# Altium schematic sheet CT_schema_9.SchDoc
size 382 x 278 mm
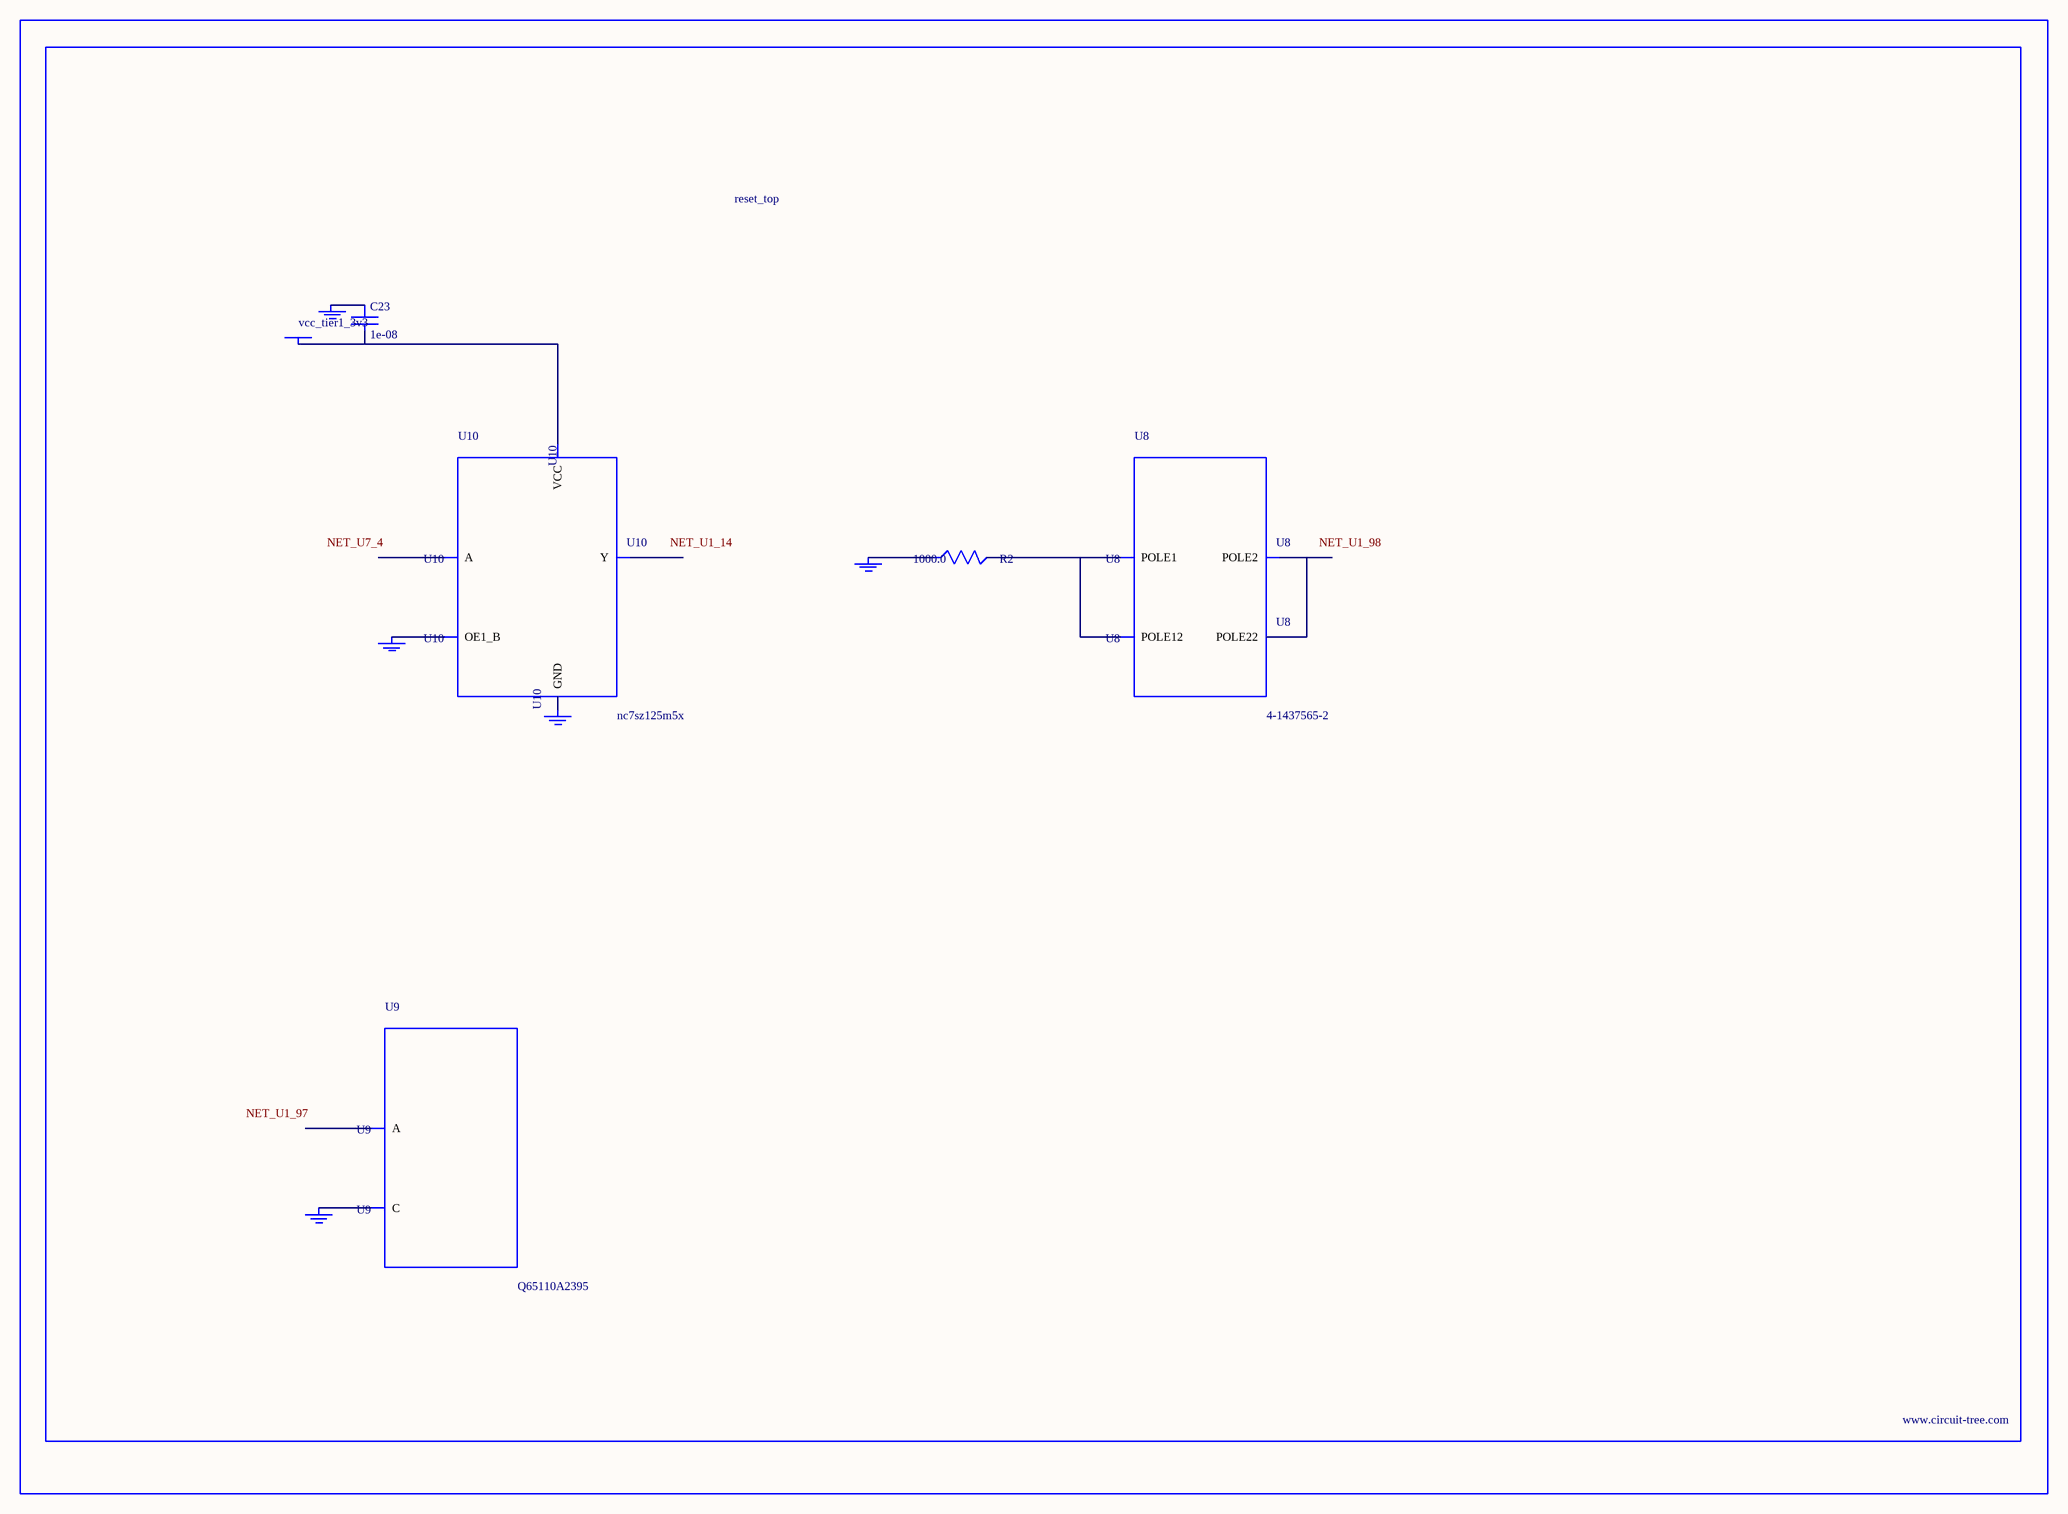
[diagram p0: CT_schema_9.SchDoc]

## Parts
BORDER8  (no value)
C23  1e-08  [C0402]
GND_INSTANCE_8_0  (no value)
GND_INSTANCE_8_1  (no value)
GND_INSTANCE_8_2  (no value)
GND_INSTANCE_8_3  (no value)
GND_INSTANCE_8_4  (no value)
POWER_INSTANCE_8_0  vcc_tier1_3v3
R2  1000.0  [R0603]
U8  4-1437565-2  [SW_4-1437565-2]
U9  Q65110A2395  [LGM67K-G1J2-24-Z]
U10  nc7sz125m5x  [NC7SZ125M5X]

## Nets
NetC23_1: C23.1 GND_INSTANCE_8_2.0(GND)
NetC23_2: C23.2 POWER_INSTANCE_8_0.0(PWR) U10.5(VCC)
NetGND_INSTANCE_8_0_0: GND_INSTANCE_8_0.0(GND) R2.1
NetGND_INSTANCE_8_1_0: GND_INSTANCE_8_1.0(GND) U9.C
NetGND_INSTANCE_8_3_0: GND_INSTANCE_8_3.0(GND) U10.1(OE1_B)
NetGND_INSTANCE_8_4_0: GND_INSTANCE_8_4.0(GND) U10.3(GND)
NetR2_2: R2.2 U8.1(POLE1) U8.2(POLE12)
NetU8_3: U8.3(POLE2) U8.4(POLE22)

Not connected (* = marked no-connect by the designer): U9 A; U10 2(A) 4(Y)

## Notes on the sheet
- Labels drawn without touching a wire or pin: NET_U1_14, NET_U1_97, NET_U1_98, NET_U7_4

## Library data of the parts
BORDER8 = BORDER_PAGE8
C23 = C0402C103K3RAC
GND_INSTANCE_8_0-GND_INSTANCE_8_4 = GND
POWER_INSTANCE_8_0 = PWR
R2 = RC0603JR-071KL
